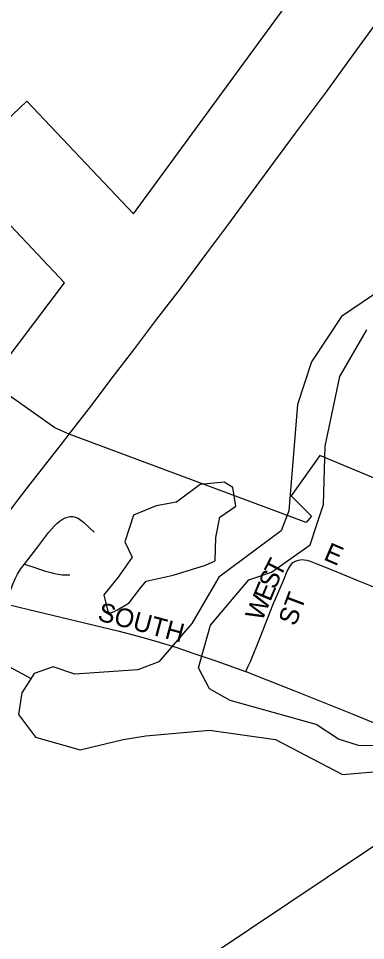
# Model space of a CAD drawing. Extents: x -49 to -8.2, y 9.4 to 23.5.
# Drawn here: x -14.1282 to -14.0404, y 15.5613 to 15.7946 of the extents above; entities that cross this region are included whole.
import ezdxf

# ---------------------------------------------------------------- set-up
doc = ezdxf.new("R2010")
doc.units = 0
for name, color, linetype in [('GM_X_City_Street', 7, 'Continuous'), ('GM_X_City_Street_Text', 7, 'Continuous'), ('GM_X_Corporation', 7, 'Continuous'), ('GM_X_Minor_Lake', 7, 'Continuous'), ('GM_X_Minor_River', 7, 'Continuous'), ('GM_X_US_Route', 7, 'Continuous')]:
    doc.layers.add(name, color=color, linetype=linetype)

msp = doc.modelspace()

# ---------------------------------------------------------------- linework, layer by layer
at = {"layer": 'GM_X_City_Street'}
for points in [[(-14.12664, 15.65659), (-14.1233, 15.66094), (-14.12046, 15.66464), (-14.11902, 15.66628), (-14.11843, 15.66684), (-14.11786, 15.66733), (-14.11736, 15.66767), (-14.11683, 15.66801), (-14.1164, 15.66823), (-14.11597, 15.66838), (-14.11552, 15.66851), (-14.11506, 15.66858), (-14.11444, 15.66857), (-14.11405, 15.66851), (-14.11354, 15.66836), (-14.11305, 15.66815), (-14.11271, 15.66793), (-14.11174, 15.66716), (-14.11007, 15.6656), (-14.10899, 15.66464)], [(-14.07067, 15.62936), (-14.07006, 15.63071), (-14.06951, 15.63193), (-14.06705, 15.638), (-14.06371, 15.64641), (-14.06115, 15.65242), (-14.06017, 15.65475), (-14.05937, 15.65625), (-14.05905, 15.65663), (-14.05872, 15.65696), (-14.05811, 15.65733), (-14.05736, 15.65757)], [(-14.05736, 15.65757), (-14.05652, 15.65771), (-14.05524, 15.65758), (-14.0544, 15.65734), (-14.0527, 15.65666), (-14.04907, 15.65522), (-14.04522, 15.65363), (-14.04218, 15.65236), (-14.03543, 15.64965), (-14.02517, 15.64548), (-14.00766, 15.6386), (-14.00389, 15.6372), (-13.99671, 15.63429), (-13.99526, 15.63366), (-13.9939, 15.63299), (-13.99301, 15.63251), (-13.99228, 15.63192), (-13.99166, 15.63125), (-13.99104, 15.6305)], [(-14.13116, 15.64642), (-14.13066, 15.64813), (-14.13034, 15.64923), (-14.12999, 15.65042), (-14.12951, 15.65166), (-14.12899, 15.65286), (-14.12843, 15.65401), (-14.12766, 15.65525), (-14.12673, 15.65647), (-14.12664, 15.65659)], [(-14.12664, 15.65659), (-14.1256, 15.65624), (-14.12454, 15.65589), (-14.12285, 15.65528), (-14.12136, 15.65481), (-14.12003, 15.65445), (-14.11907, 15.65421), (-14.11811, 15.65405), (-14.11716, 15.65389), (-14.11604, 15.65381), (-14.11514, 15.65388)], [(-14.13116, 15.64642), (-14.12558, 15.64512), (-14.10301, 15.63971), (-14.0979, 15.63831), (-14.0934, 15.63709), (-14.08834, 15.63554), (-14.08384, 15.63399), (-14.07798, 15.63198), (-14.07076, 15.6294), (-14.07067, 15.62936)], [(-14.07067, 15.62936), (-14.06537, 15.62729), (-14.05853, 15.62457), (-14.04377, 15.61866), (-14.03166, 15.61375), (-14.02947, 15.61295), (-14.027, 15.61201), (-14.0247, 15.61122), (-14.02371, 15.61103), (-14.02296, 15.61089), (-14.02207, 15.61089)]]:
    msp.add_lwpolyline(points, dxfattribs=at)
at = {"layer": 'GM_X_Corporation'}
for points in [[(-13.96507, 15.64785), (-14.05192, 15.68406), (-14.05919, 15.67384), (-14.05401, 15.66868), (-14.05538, 15.6671), (-14.11536, 15.6894), (-14.11896, 15.69104), (-14.13548, 15.70267), (-14.11654, 15.72767), (-14.14392, 15.75671), (-14.12603, 15.77362), (-14.09909, 15.74512), (-14.04416, 15.82019), (-14.07436, 15.85547), (-14.12761, 15.84615), (-14.12922, 15.93057), (-14.13238, 16.04805), (-14.17924, 16.04568), (-14.18534, 16.20866)], [(-13.97157, 15.44046), (-14.06379, 15.43387), (-14.0886, 15.41233), (-14.09352, 15.41807), (-14.10501, 15.43117), (-14.07786, 15.433), (-14.08392, 15.47838), (-14.04762, 15.48571), (-14.0508, 15.50967), (-14.07191, 15.50824), (-14.08114, 15.52328), (-14.09132, 15.5165), (-14.09256, 15.51924), (-14.08882, 15.52172), (-14.09486, 15.53081), (-14.09535, 15.53327), (-14.09668, 15.5462), (-14.07943, 15.55775), (-13.97147, 15.63)]]:
    msp.add_lwpolyline(points, dxfattribs=at)
at = {"layer": 'GM_X_Minor_Lake'}
for points in [[(-14.08906, 15.6538), (-14.08086, 15.65633), (-14.07837, 15.65743), (-14.07828, 15.66331), (-14.07725, 15.66842), (-14.07322, 15.6712), (-14.0739, 15.67596), (-14.07615, 15.67732), (-14.08224, 15.67666), (-14.08819, 15.6722), (-14.09333, 15.67133), (-14.09907, 15.66896), (-14.10126, 15.66216), (-14.09943, 15.65833), (-14.10292, 15.65327), (-14.1066, 15.64877), (-14.10553, 15.64457)], [(-14.10553, 15.64457), (-14.10485, 15.64417), (-14.10326, 15.64494), (-14.10021, 15.64681), (-14.09743, 15.65034), (-14.09584, 15.65221), (-14.08906, 15.6538)]]:
    msp.add_lwpolyline(points, dxfattribs=at)
at = {"layer": 'GM_X_Minor_River'}
for points in [[(-14.0357, 15.72641), (-14.04644, 15.71918), (-14.05403, 15.70772), (-14.05762, 15.69696), (-14.05976, 15.67004), (-14.06174, 15.66494), (-14.07749, 15.65324), (-14.08432, 15.64158), (-14.09264, 15.63184), (-14.09799, 15.62984), (-14.11395, 15.62876), (-14.11942, 15.63056), (-14.1242, 15.62893), (-14.12731, 15.62404), (-14.12816, 15.61855), (-14.12389, 15.61279), (-14.11255, 15.60957), (-14.10169, 15.61224), (-14.09598, 15.6131), (-14.07983, 15.61455), (-14.06316, 15.61219), (-14.04622, 15.60338), (-14.03634, 15.60417)], [(-14.0313, 15.61054), (-14.04212, 15.61072), (-14.04722, 15.61232), (-14.05285, 15.61601), (-14.07458, 15.62206), (-14.07985, 15.62499), (-14.08261, 15.63035), (-14.07959, 15.64112), (-14.06991, 15.65255), (-14.06419, 15.65454), (-14.0544, 15.66141), (-14.0528, 15.66632), (-14.05101, 15.6716), (-14.05058, 15.6864), (-14.04688, 15.704), (-14.04004, 15.71585)], [(-14.12505, 15.6276), (-14.13702, 15.63407), (-14.14196, 15.63377), (-14.14318, 15.61086)]]:
    msp.add_lwpolyline(points, dxfattribs=at)
at = {"layer": 'GM_X_US_Route'}
for points in [[(-14.11536, 15.6894), (-14.10967, 15.6967), (-14.10445, 15.70366), (-14.09896, 15.7108), (-14.09313, 15.71848), (-14.08726, 15.7261), (-14.0808, 15.73485), (-14.07519, 15.7423), (-14.06707, 15.7533), (-14.05808, 15.76558), (-14.05026, 15.77604), (-14.04459, 15.78382), (-14.03688, 15.79436)], [(-14.13379, 15.66569), (-14.13217, 15.6677), (-14.12833, 15.6727), (-14.12611, 15.6756), (-14.11731, 15.6869), (-14.11536, 15.6894)]]:
    msp.add_lwpolyline(points, dxfattribs=at)

# ---------------------------------------------------------------- texts
at = {"layer": 'GM_X_City_Street_Text'}
for s, height, rotation, p in [('E', 0.00473, 336.7863, (-14.05122, 15.65779)), ('T', 0.00473, 62.6284, (-14.06196, 15.65294)), ('S', 0.00473, 67.3373, (-14.0632, 15.64996)), ('E', 0.00473, 67.3319, (-14.06448, 15.64688)), ('W', 0.00473, 67.318, (-14.06657, 15.64188)), ('ST', 0.004735, 69.4499, (-14.05812, 15.64068)), ('SOUTH', 0.004735, 345.0677, (-14.10839, 15.64241))]:
    msp.add_text(s, height=height, rotation=rotation, dxfattribs=at).set_placement(p)

doc.saveas('drawing.dxf')
